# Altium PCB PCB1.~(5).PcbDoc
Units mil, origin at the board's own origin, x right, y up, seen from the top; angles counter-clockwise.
Board outline 6000 x 4000 mil, 2 copper layers (Top Layer, Bottom Layer); 23 components, 29 nets, 107 pads, 17 vias.
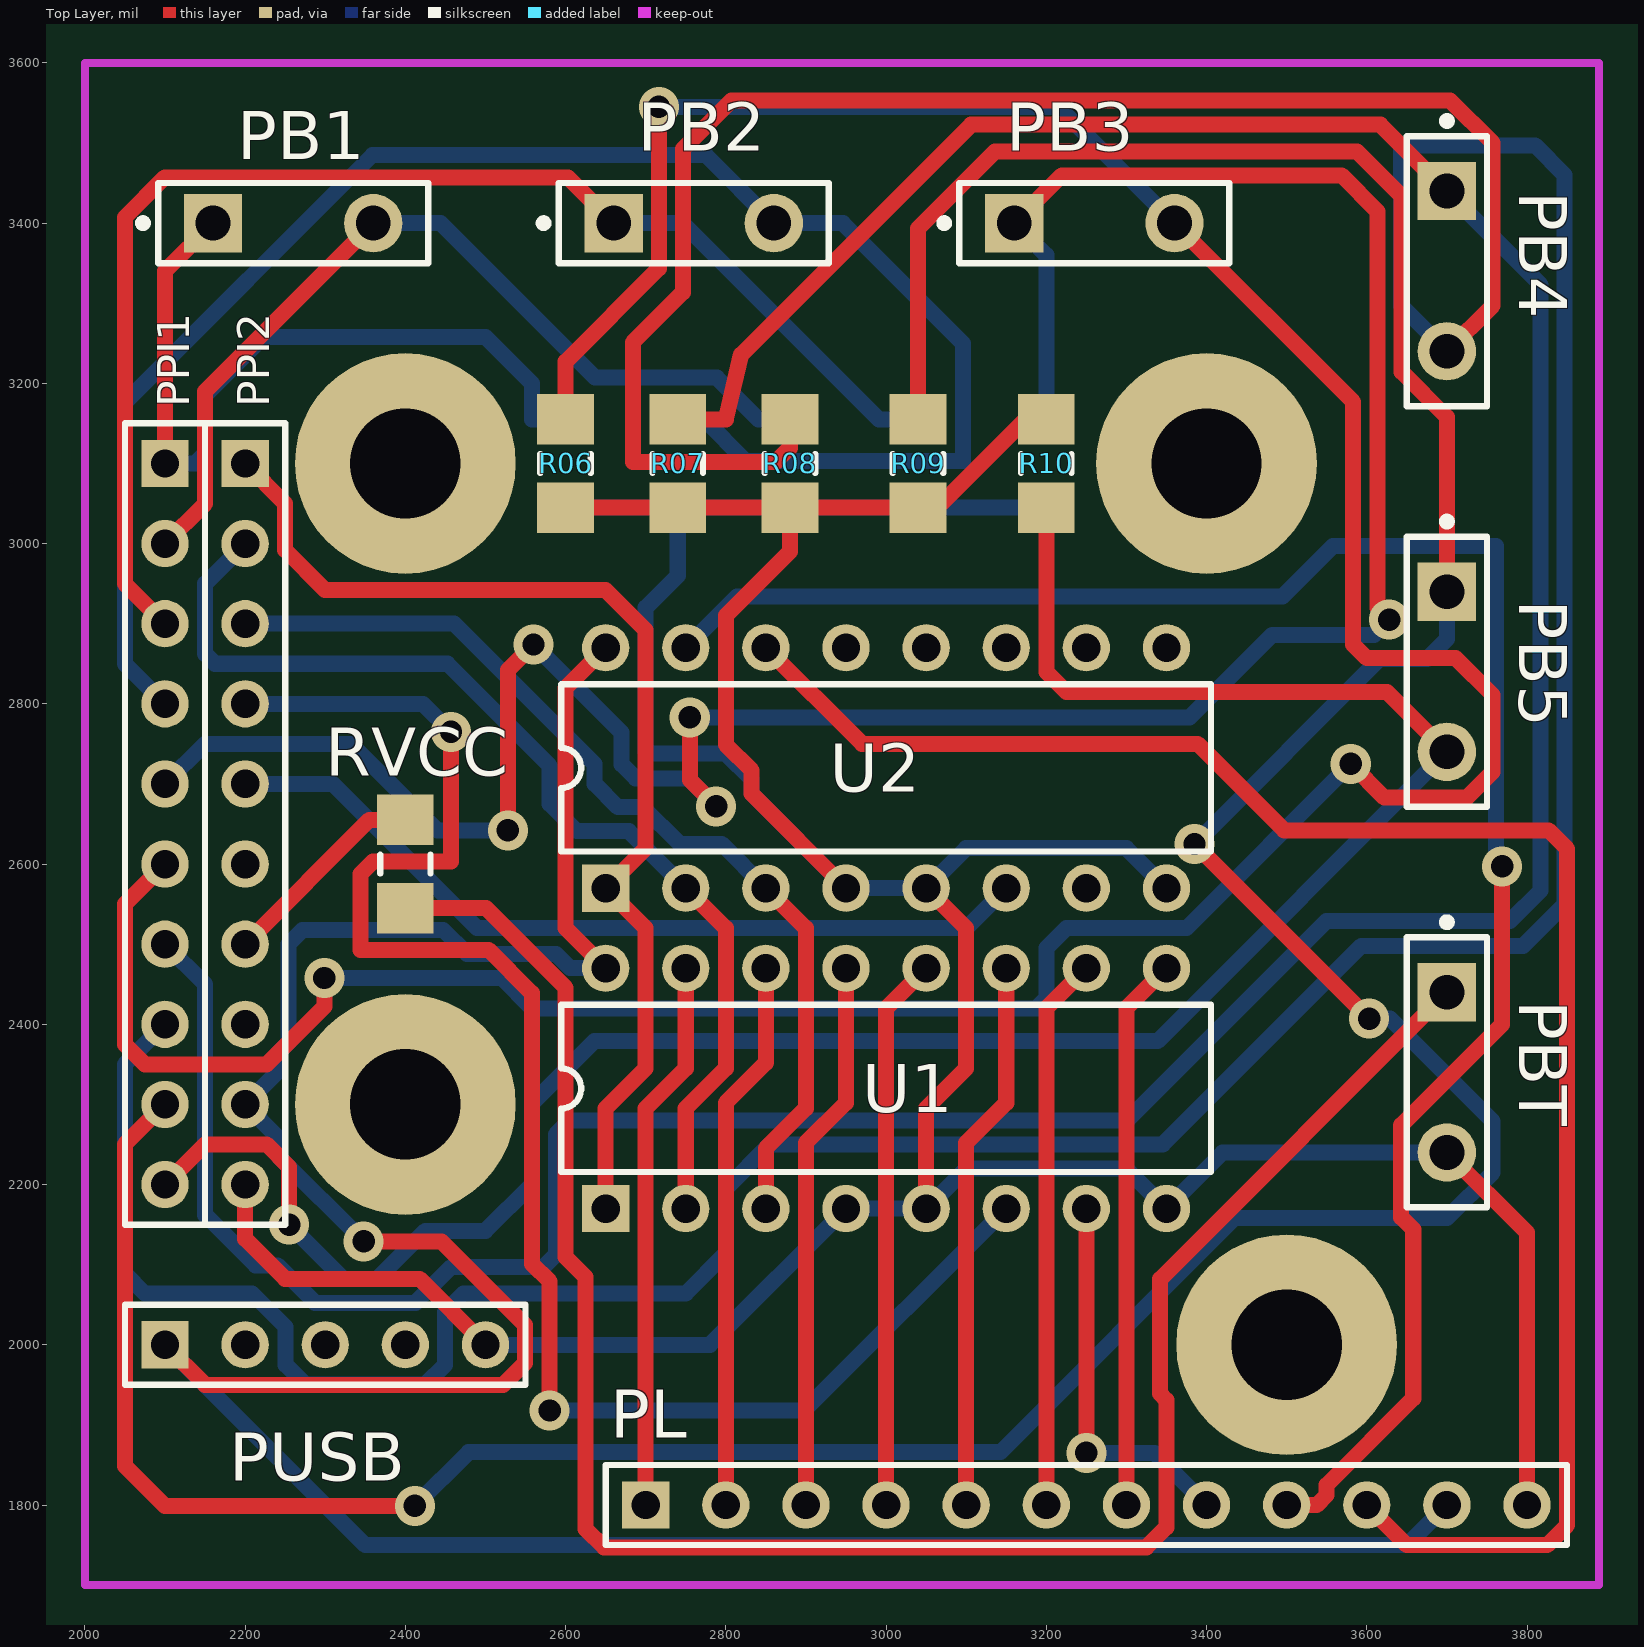
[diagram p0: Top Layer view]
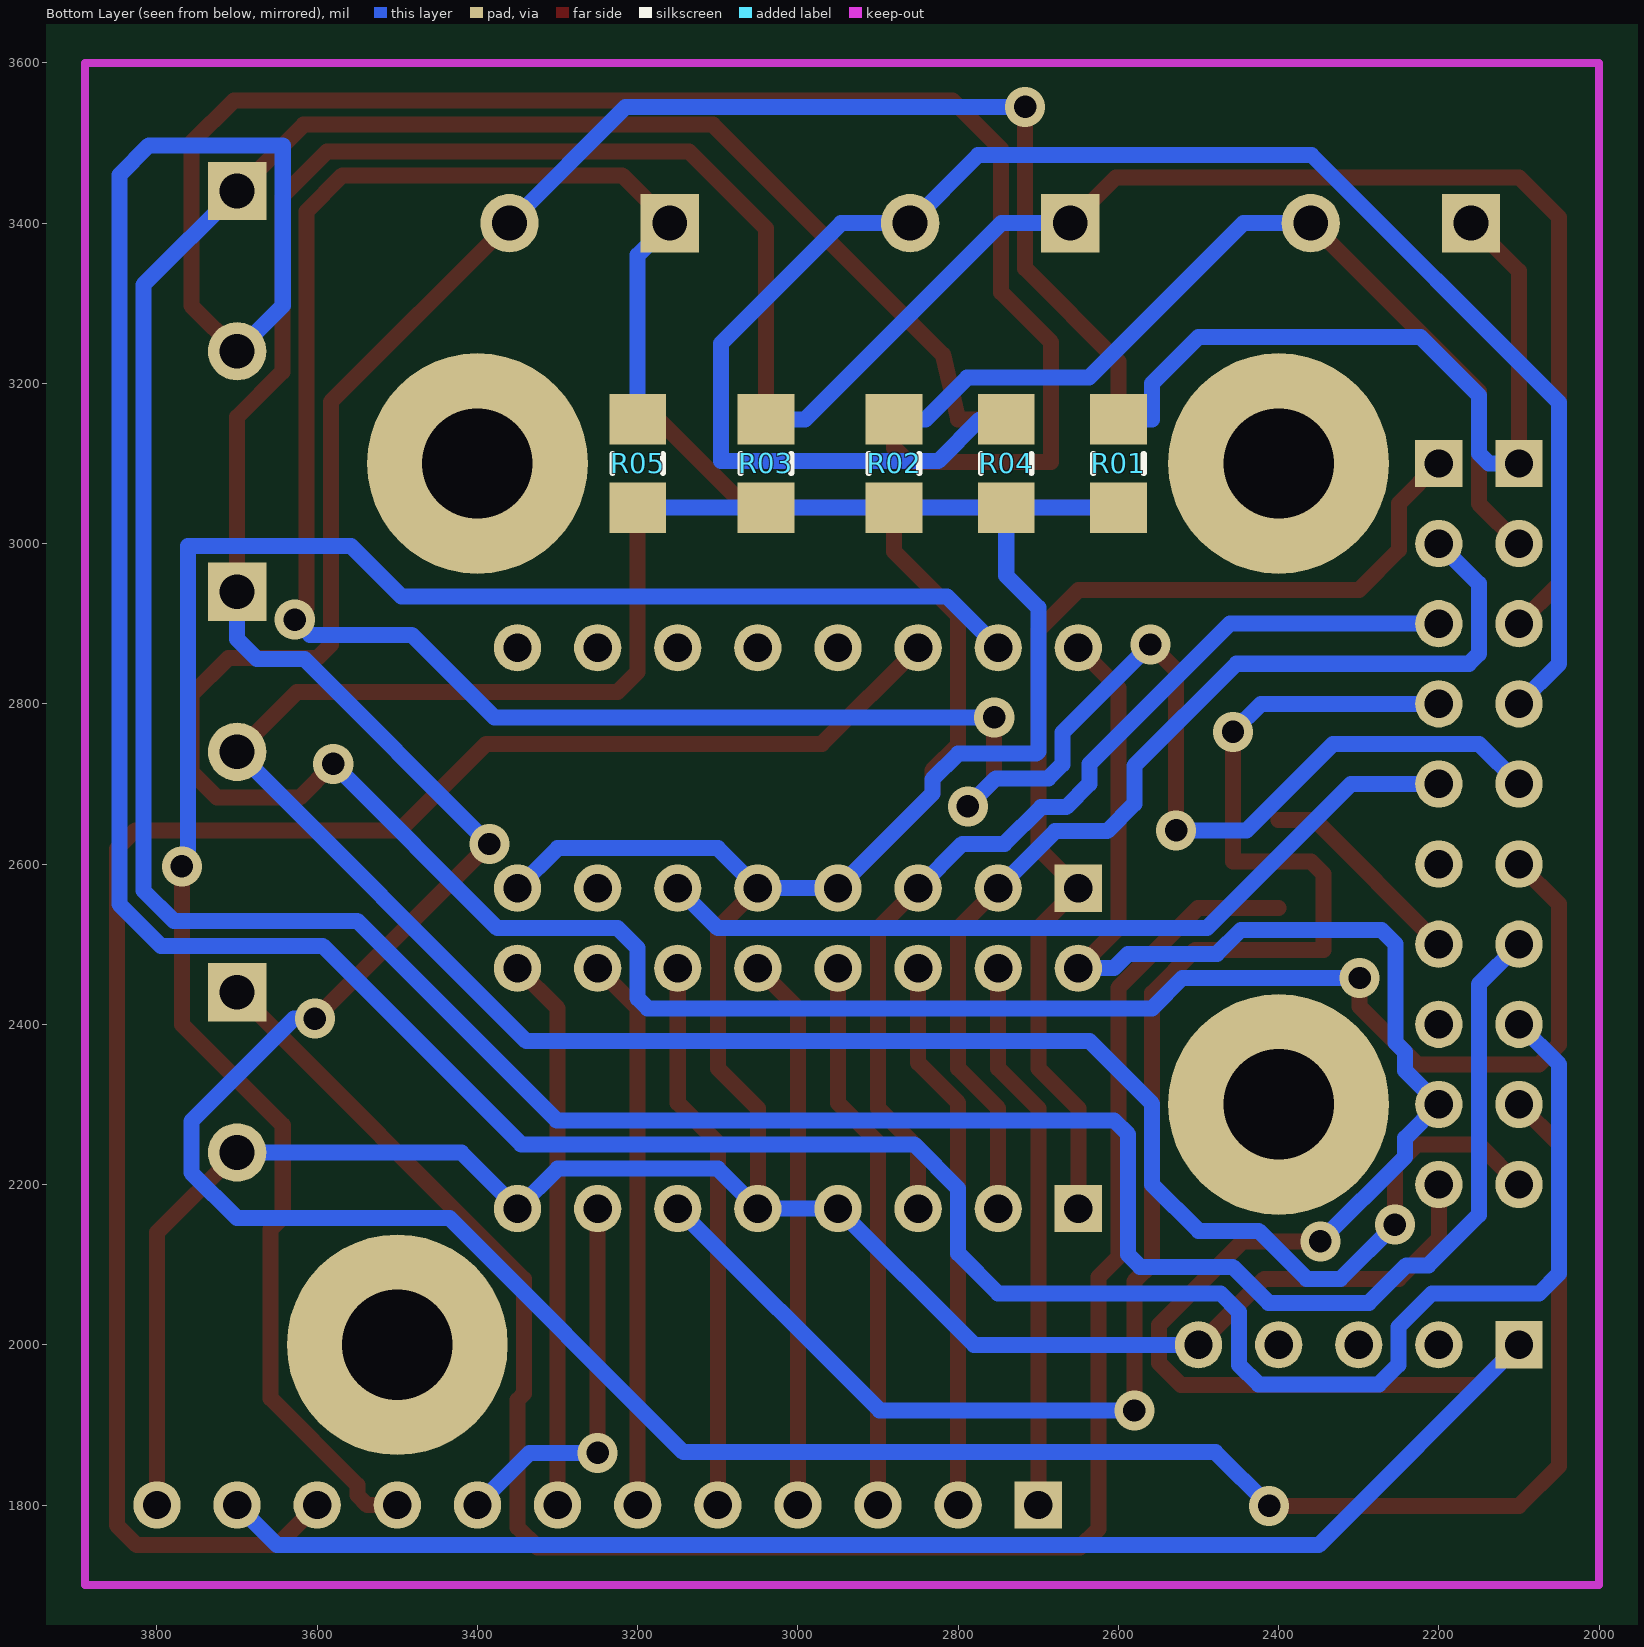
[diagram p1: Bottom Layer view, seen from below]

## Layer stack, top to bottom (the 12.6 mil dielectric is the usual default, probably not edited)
Top Layer: signal copper 1.4
Dielectric: dielectric 12.6, FR-4, Dk 4.8
Bottom Layer: signal copper 1.4

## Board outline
1000,1000 7000,1000 7000,5000 1000,5000

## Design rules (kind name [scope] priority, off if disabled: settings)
Clearance [All] p1: gap=10
ComponentClearance [All] p1: gap=10 collisioncheckmode=3 verticalgap=10
PolygonConnect [All] p1: connectstyle=Relief reliefconductorwidth=10 reliefentries=4 polygonreliefangle="90 Angle"
RoutingVias [All] p1: holewidth=28 width=50 viastyle="Through Hole" minholewidth=28 minwidth=50 maxholewidth=28 maxwidth=50
SolderMaskExpansion [All] p1: expansion=4
TestPointUsage [All] p1: valid=0 allowmultiple=FALSE
Testpoint [All] p1: side=15 testpointundercomponent=TRUE minsize=40 maxsize=100 preferedsize=60 minholesize=0 maxholesize=40 preferedholesize=32 testpointgrid=1 style=1023 order=0123456789
Width Width_2 [All] p1: maxlimit=30 minlimit=15 preferedwidth=20
Width Width_1 [InNet('VCC')] p2: maxlimit=30 minlimit=20 preferedwidth=30
Width [InNet('GND')] p3: maxlimit=30 minlimit=20 preferedwidth=30
18 further rules are at their usual default settings.

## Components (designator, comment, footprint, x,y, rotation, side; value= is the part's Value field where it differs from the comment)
PB1 "Header 2" SPST-2 2260,3400 r0 top
PB2 "Header 2" SPST-2 2760,3400 r0 top
PB3 "Header 2" SPST-2 3260,3400 r0 top
PB4 "Header 2" SPST-2 3700,3340 r270 top
PB5 "Header 2" SPST-2 3700,2840 r270 top
PBT "Header 2" SPST-2 3700,2340 r270 top
PL "Header 12" HDR1X12 2700,1800 r0 top
PPI1 "Header 10" HDR1X10 2100,3100 r270 top
PPI2 "Header 10" HDR1X10 2200,3100 r270 top
PUSB "Header 5" HDR1X5 2100,2000 r0 top
R01 "Res1" 3216[1206] 2600,3100 r90 bottom
R02 "Res1" 3216[1206] 2880,3100 r90 bottom
R03 "Res1" 3216[1206] 3040,3100 r90 bottom
R04 "Res1" 3216[1206] 2740,3100 r90 bottom
R05 "Res1" 3216[1206] 3200,3100 r90 bottom
R06 "Res1" 3216[1206] 2600,3100 r90 top
R07 "Res1" 3216[1206] 2740,3100 r90 top
R08 "Res1" 3216[1206] 2880,3100 r90 top
R09 "Res1" 3216[1206] 3040,3100 r90 top
R10 "Res1" 3216[1206] 3200,3100 r270 top
RVCC "Res1" 3216[1206] 2400,2600 r90 top
U1 "SN74HC138D" DIP-16 3000,2320 r0 top
U2 "SN74HC138D" DIP-16 3000,2720 r0 top

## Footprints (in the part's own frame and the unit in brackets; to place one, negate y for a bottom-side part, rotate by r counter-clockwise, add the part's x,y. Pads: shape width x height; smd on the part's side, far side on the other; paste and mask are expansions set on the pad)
3216[1206] [mm] "Chip Resistor; Body 3.2 x 1.6 mm (LxW typ)"
  rect 1.6x1.8 smd: 1(-1.4,0) 2(1.4,0)
  silkscreen extent -0.3,-0.8 0.3,0.8
DIP-16 [mm] "DIP; 16 Leads; Row Spacing 7.62 mm; Pitch 2.54 mm"
  rect 1.5x1.5 hole 0.9: 1(-8.89,-3.81)
  round 1.5 hole 0.9: 2(-6.35,-3.81) 3(-3.81,-3.81) 4(-1.27,-3.81) 5(1.27,-3.81) 6(3.81,-3.81) 7(6.35,-3.81) 8(8.89,-3.81) 9(8.89,3.81) 10(6.35,3.81) 11(3.81,3.81) 12(1.27,3.81) 13(-1.27,3.81) 14(-3.81,3.81) 15(-6.35,3.81) 16(-8.89,3.81)
  silkscreen extent -10.3,-2.65 10.3,2.65
HDR1X5 [mm] "Connector; Header; 5 Position"
  rect 1.5x1.5 hole 0.9: 1(0,0)
  round 1.5 hole 0.9: 2(2.54,0) 3(5.08,0) 4(7.62,0) 5(10.16,0)
  silkscreen extent -1.27,-1.27 11.43,1.27
HDR1X10 [mm] "Connector; Header; 10 Position"
  rect 1.5x1.5 hole 0.9: 1(0,0)
  round 1.5 hole 0.9: 2(2.54,0) 3(5.08,0) 4(7.62,0) 5(10.16,0) 6(12.7,0) 7(15.24,0) 8(17.78,0) 9(20.32,0) 10(22.86,0)
  silkscreen extent -1.27,-1.27 24.13,1.27
HDR1X12 [mm] "Connector; Header; 12 Position"
  rect 1.5x1.5 hole 0.9: 1(0,0)
  round 1.5 hole 0.9: 2(2.54,0) 3(5.08,0) 4(7.62,0) 5(10.16,0) 6(12.7,0) 7(15.24,0) 8(17.78,0) 9(20.32,0) 10(22.86,0) 11(25.4,0) 12(27.94,0)
  silkscreen extent -1.27,-1.27 29.21,1.27
SPST-2 [mm] "Circuit Breaker; 2 Leads"
  rect 1.85x1.85 hole 1.1: 1(-2.54,0)
  round 1.85 hole 1.1: 2(2.54,0)
  silkscreen extent -4.89,-1.27 4.28,1.27

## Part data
PB1 PB2 PB3 PB4 PB5 PBT: "Header, 2-Pin"
PL: "Header, 12-Pin"
PPI1 PPI2: "Header, 10-Pin"
PUSB: "Header, 5-Pin"
R01 R02 R03 R04 R05 R06 R07 R08 R09 R10 RVCC: "Resistor"
U1 U2: "3-Line to 8-Line Decoder / Demultiplexer"

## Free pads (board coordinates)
  round 275.59 hole 137.8: 0(3400,3100) 1(2400,3100) 3(3500,2000)
  round 275.59 hole 137.8 paste+0: 2(2400,2300)

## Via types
v1: diameter 50, hole 28, Top Layer to Bottom Layer, 17 vias

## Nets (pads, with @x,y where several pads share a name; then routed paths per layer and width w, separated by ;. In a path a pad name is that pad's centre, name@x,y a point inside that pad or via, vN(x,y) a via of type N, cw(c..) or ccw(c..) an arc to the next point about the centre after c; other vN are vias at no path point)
GND: PBT.2 PL.12 PPI2.10 PUSB.5 R01.1 R02.1 R03.1 R04.1 R05.1 R06.1 R07.1 R08.1 R09.1 R10.1 U1.4 U1.5 U1.8 U2.4 U2.5 U2.8 | length 5595.4
  Top Layer w20: PPI2.10 2200,2132.2 2250,2082.2 2417.8,2082.2 PUSB.5 ; R06.1 R07.1 R08.1 ; U2.4 2832.21,2687.79 2832.21,2716.96 2800,2749.17 2800,2910 2880,2990 R08.1 ; U1.5 3050,2295 3100,2345 3100,2520 U2.5 ; R10.1 3174.24,3155.12 3064,3044.88 R09.1 R08.1 ; PBT.2 3800,2140 PL.12
  Bottom Layer w20: PUSB.5 2780,2000 U1.4 U1.5 3100,2220 3300,2220 U1.8 3420,2240 PBT.2 ; R01.1 R04.1 ; R05.1 R03.1 R02.1 R04.1 ; U2.8 3300,2620 3100,2620 U2.5 U2.4 2832.21,2687.79 2832.21,2705.59 2800,2737.79 2702.78,2737.79 2700,2740.57 2700,2920 2740,2960 R04.1
NetPB1_1: PB1.1 PPI1.1 R01.2 | length 1001.7
  Top Layer w20: PPI1.1 2100,3340 PB1.1
  Bottom Layer w20: PPI1.1 2137.5,3100 2150,3112.5 2150,3185 2223,3258 2500,3258 2558,3200 2558,3155.12 R01.2
NetPB1_2: PB1.2 PPI1.2 R02.2 | length 1129.1
  Top Layer w20: PPI1.2 2150,3050 2150,3190 PB1.2
  Bottom Layer w20: PB1.2 2444,3400 2637,3207 2788.83,3207 2840.71,3155.12 R02.2
NetPB2_1: PB2.1 PPI1.3 R03.2 | length 1663.5
  Top Layer w20: PPI1.3 2050,2950 2050,3407 2100,3457 2603,3457 PB2.1
  Bottom Layer w20: PB2.1 2746.12,3400 2991,3155.12 R03.2
NetPB2_2: PB2.2 PPI1.4 R04.2 | length 2192.6
  Bottom Layer w20: PPI1.4 2050,2850 2050,3176 2359,3485 2775,3485 PB2.2 2946,3400 3096,3250 3096,3103 2825,3103 2772.88,3155.12 R04.2
NetPB3_1: PB3.1 PPI1.5 R05.2 | length 3395.5
  Top Layer w20: v1(2528,2642) 2528,2842 v1(2560,2874) ; v1(2755,2783) 2755,2705 v1(2788,2672) ; PB3.1 3219.5,3459.5 3568.5,3459.5 3613.58,3414.42 3613.58,2919.42 v1(3628,2905)
  Bottom Layer w20: PPI1.5 2150,2750 2332,2750 2440,2642 v1(2528,2642) ; v1(2560,2874) 2670,2764 2670,2724.5 2687.5,2707 2753,2707 v1(2788,2672) ; v1(2755,2783) 3379,2783 3482,2886 3609,2886 v1(3628,2905) ; PB3.1 3200,3360 R05.2
NetPB3_2: PB3.2 PPI1.6 R06.2 | length 4294.1
  Top Layer w20: PPI1.6 2050,2550 2050,2375 2075,2350 2226.84,2350 2299,2422.16 v1(2299,2457.8) ; R06.2 2600,3227.16 2716.42,3343.58 v1(2716.42,3545) ; PB3.2 3583,3177 3583,2874 3600,2857 3711,2857 3757,2811 3757,2715 3725,2683 3622,2683 v1(3580,2725)
  Bottom Layer w20: v1(2299,2457.8) 2520.2,2457.8 2558,2420 3187.5,2420 3200,2432.5 3200,2495 3225,2520 3375,2520 v1(3580,2725) ; v1(2716.42,3545) 3215,3545 PB3.2
NetPB4_1: PB4.1 PPI1.7 R07.2 | length 4470.9
  Top Layer w20: R07.2 2800,3155.12 2819,3235.76 3106.24,3523 3617,3523 PB4.1
  Bottom Layer w20: PPI1.7 2150,2450 2150,2162.2 2213.05,2099.16 2240.55,2099.16 2287.5,2052.2 2412.5,2052.2 2457.5,2097.2 2572.8,2097.2 2588,2112.41 2588,2262.5 2605.5,2280 3301.02,2280 3550.02,2529 3779,2529 3817,2567 3817,3323 PB4.1
NetPB4_2: PB4.2 PPI1.8 R08.2 | length 5954.5
  Top Layer w20: R08.2 2880,3119.5 2862.5,3102 2684,3102 2684,3251.16 2746.42,3313.58 2746.42,3492.42 2807,3553 3704,3553 3757,3500 3757,3297 PB4.2
  Bottom Layer w20: PPI1.8 2050,2350 2050,2089 2075,2064 2208.68,2064 2250.47,2022.2 2250.47,1975 2275,1950.47 2425,1950.47 2449.53,1975 2449.53,2040.99 2472.53,2064 2750,2064 2800,2114 2800,2195 2855,2250 3345.33,2250 3593.33,2498 3795,2498 3847,2550 3847,3460 3810,3497 3643,3497 3643,3297 PB4.2
NetPB5_1: PB5.1 PPI1.9 R09.2 | length 4853
  Top Layer w20: PPI1.9 2050,2250 2050,1849 2100,1799 v1(2412,1799) ; R09.2 3040,3393.42 3136.08,3489.5 3587.5,3489.5 3643.58,3433.42 3643.58,3214.42 3700,3158 PB5.1 ; v1(3385,2625) v1(3603,2407)
  Bottom Layer w20: v1(2412,1799) 2479,1866 3142.84,1866 3434.84,2158 3700,2158 3757,2215 3757,2279 3629,2407 v1(3603,2407) ; v1(3385,2625) 3615.71,2855.71 3675,2855.71 3700,2880.71 PB5.1
NetPB5_2: PB5.2 PPI1.10 R10.2 | length 2810.1
  Top Layer w20: PPI1.10 2150,2250 2226.84,2250 2255,2221.84 v1(2255,2150) ; R10.2 3200,2840 3225,2815 3625,2815 PB5.2
  Bottom Layer w20: v1(2255,2150) 2322.8,2082.2 2365,2082.2 2425,2142.2 2500,2142.2 2557.8,2200 2557.8,2300.8 2636,2379 3339,2379 PB5.2
NetPBT_1: PBT.1 RVCC.1 | length 2491.6
  Top Layer w20: RVCC.1 2500.71,2544.88 2600,2445.59 2600,2109.53 2625,2084.53 2625,1770 2648,1747 3325,1747 3350,1772 3350,1931 3342,1939 3342,2082 PBT.1
NetPL_1: PL.1 U1.15 | length 690.7
  Top Layer w20: PL.1 2700,2295 2750,2345 U1.15
NetPL_2: PL.2 U1.14 | length 690.7
  Top Layer w20: PL.2 2800,2302 2850,2352 U1.14
NetPL_3: PL.3 U1.13 | length 690.7
  Top Layer w20: PL.3 2900,2252 2950,2302 U1.13
NetPL_4: PL.4 U1.12 | length 690.7
  Top Layer w20: PL.4 3000,2420 U1.12
NetPL_5: PL.5 U1.11 | length 690.7
  Top Layer w20: PL.5 3100,2252 3150,2302 U1.11
NetPL_6: PL.6 U1.10 | length 690.7
  Top Layer w20: PL.6 3200,2420 U1.10
NetPL_7: PL.7 U1.9 | length 690.7
  Top Layer w20: PL.7 3300,2420 U1.9
NetPL_8: PL.8 U1.7 | length 481.9
  Top Layer w20: v1(3250,1865) U1.7
  Bottom Layer w20: v1(3250,1865) 3335,1865 PL.8
NetPL_9: PL.9 U2.15 | length 2409.7
  Top Layer w20: PL.9 3537.5,1800 3550,1812.5 3550,1825 3658,1933 3658,2144 3643,2159 3643,2274 3769,2400 v1(3769,2597)
  Bottom Layer w20: U2.15 2814,2934 3495,2934 3558,2997 3761,2997 3761,2605 v1(3769,2597)
NetPL_10: PL.10 U2.14 | length 2229
  Top Layer w20: U2.14 2970,2750 3389,2750 3497,2642 3827,2642 3850,2619 3850,1775 3825,1750 3650,1750 PL.10
NetPPI2_1: PPI2.1 U1.1 U2.1 | length 1404.3
  Top Layer w20: PPI2.1 2250,3050 2250,2992 2300,2942 2650,2942 2700,2892 2700,2620 U2.1 2700,2520 2700,2345 2650,2295 U1.1
NetPPI2_2: PPI2.2 U1.2 U2.2 | length 1348.7
  Top Layer w20: U1.2 2750,2295 2800,2345 2800,2520 U2.2
  Bottom Layer w20: PPI2.2 2150,2950 2150,2862.5 2162.5,2850 2452.61,2850 2580,2722.61 2580,2675 2614.03,2640.97 2679.03,2640.97 U2.2
NetPPI2_3: PPI2.3 U1.3 U2.3 | length 1242.6
  Top Layer w20: U1.3 2850,2245 2900,2295 2900,2520 U2.3
  Bottom Layer w20: PPI2.3 2460.94,2900 2636.26,2724.69 2636.26,2700 2665.28,2670.97 2696.37,2670.97 2742.21,2625.13 2794.87,2625.13 U2.3
NetPPI2_4: PPI2.4 U1.6 | length 2088.3
  Top Layer w20: v1(2457,2765) 2457,2603 2359.5,2603 2344,2587.5 2344,2493 2504,2493 2558,2439 2558,2101.06 2580,2079.06 v1(2580,1918)
  Bottom Layer w20: PPI2.4 2422,2800 v1(2457,2765) ; v1(2580,1918) 2898,1918 U1.6
NetPPI2_5: PPI2.5 U2.6 | length 1045.3
  Bottom Layer w20: PPI2.5 2309.53,2700 2489.53,2520 3100,2520 U2.6
NetPPI2_7: PPI2.7 RVCC.2 | length 264.3
  Top Layer w20: PPI2.7 2355.12,2655.12 RVCC.2
VCC: PL.11 PPI2.9 PUSB.1 U1.16 U2.16 | length 3817
  Top Layer w20: PUSB.1 2150,1950 2522,1950 2549.53,1977.53 2549.53,2024.47 2445,2129 v1(2347.84,2129) ; U1.16 2600,2520 2600,2820 U2.16
  Bottom Layer w20: PUSB.1 2350,1750 3650,1750 PL.11 ; v1(2347.84,2129) 2242.2,2234.64 2242.2,2257.8 PPI2.9 2242.2,2342.2 2242.2,2365.36 2254,2377.16 2254,2500 2271.8,2517.8 2447,2517.8 2477,2487.8 2587.8,2487.8 2605.59,2470 U1.16
pads on no net: PPI2.6 PPI2.8 PUSB.2 PUSB.3 PUSB.4 U2.7 U2.9 U2.10 U2.11 U2.12 U2.13

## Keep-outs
Keep-Out Layer:
  lines w10: 2000,1700 2000,3600 3890,3600 3890,1700 2000,1700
